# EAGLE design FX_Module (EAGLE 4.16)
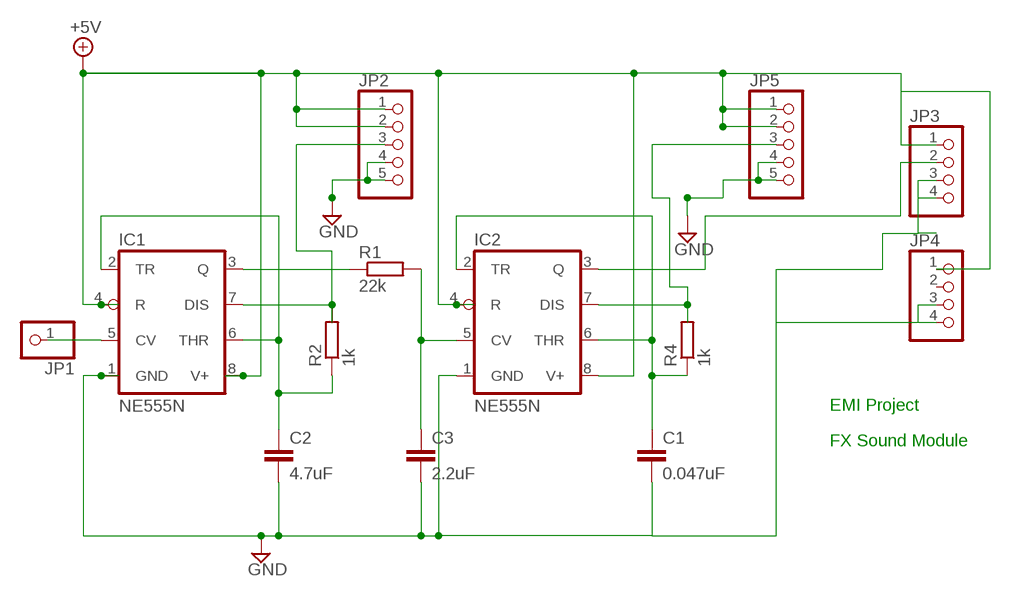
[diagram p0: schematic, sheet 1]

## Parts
C1  0.047uF  C-EU025-024X044  [C025-024X044]
C2  4.7uF  C-EU025-024X044  [C025-024X044]
C3  2.2uF  C-EU025-024X044  [C025-024X044]
IC1  NE555N  [DIL08]
IC2  NE555N  [DIL08]
JP1  PINHD-1X1  [1X01]
JP2  PINHD-1X5  [1X05]
JP3  PINHD-1X4  [1X04]
JP4  PINHD-1X4  [1X04]
JP5  PINHD-1X5  [1X05]
R1  22k  R-EU_0204/7  [0204/7]
R2  1k  R-EU_0204/7  [0204/7]
R4  1k  R-EU_0204/7  [0204/7]

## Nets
+5V: IC1.4(R) IC1.8(V+) IC2.4(R) IC2.8(V+) JP2.1 JP2.2 JP3.1 JP4.1 JP5.1 JP5.2
GND: C1.2 C2.2 C3.2 IC1.1(GND) IC2.1(GND) JP2.4 JP2.5 JP3.3 JP3.4 JP4.3 JP4.4 JP5.4 JP5.5
N$1: C3.1 IC2.5(CV) R1.2
N$2: IC2.7(DIS) JP5.3 R4.2
N$3: IC1.7(DIS) JP2.3 R2.2
N$4: IC2.3(Q) JP3.2
N$6: IC1.5(CV) JP1.1
N$7: C2.1 IC1.2(TR) IC1.6(THR) R2.1
N$8: C1.1 IC2.2(TR) IC2.6(THR) R4.1
N$10: IC1.3(Q) R1.1
Unconnected: JP4.2

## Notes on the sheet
- EMI Project
- FX Sound Module

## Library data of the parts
C1-C3 = rcl:C-EU: CAPACITOR, European symbol
IC1 IC2 = linear:*555: TIMER
JP1 = pinhead:PINHD-1X1: PIN HEADER
JP2 JP5 = pinhead:PINHD-1X5: PIN HEADER
JP3 JP4 = pinhead:PINHD-1X4: PIN HEADER
R1 R2 R4 = rcl:R-EU_: RESISTOR, European symbol

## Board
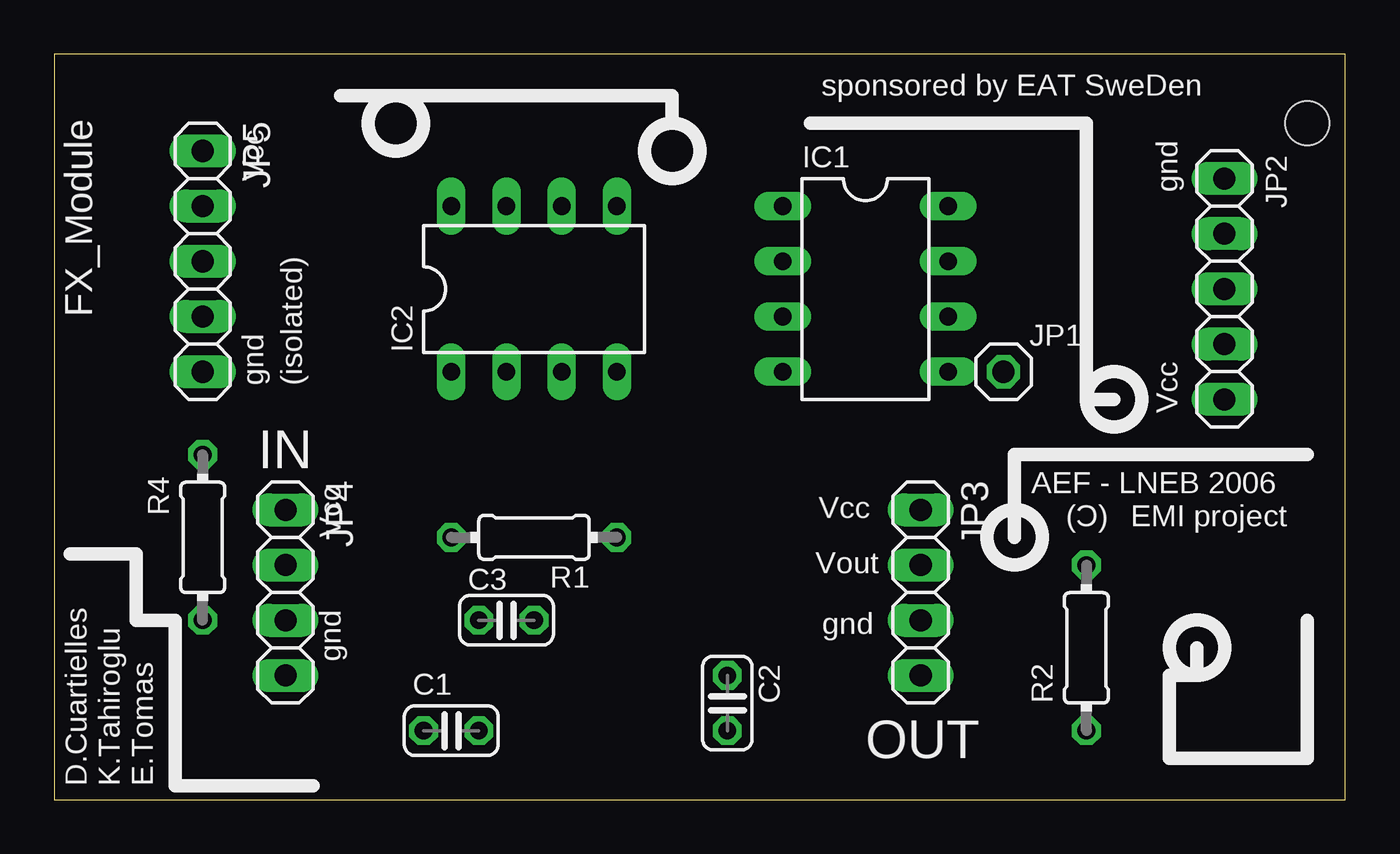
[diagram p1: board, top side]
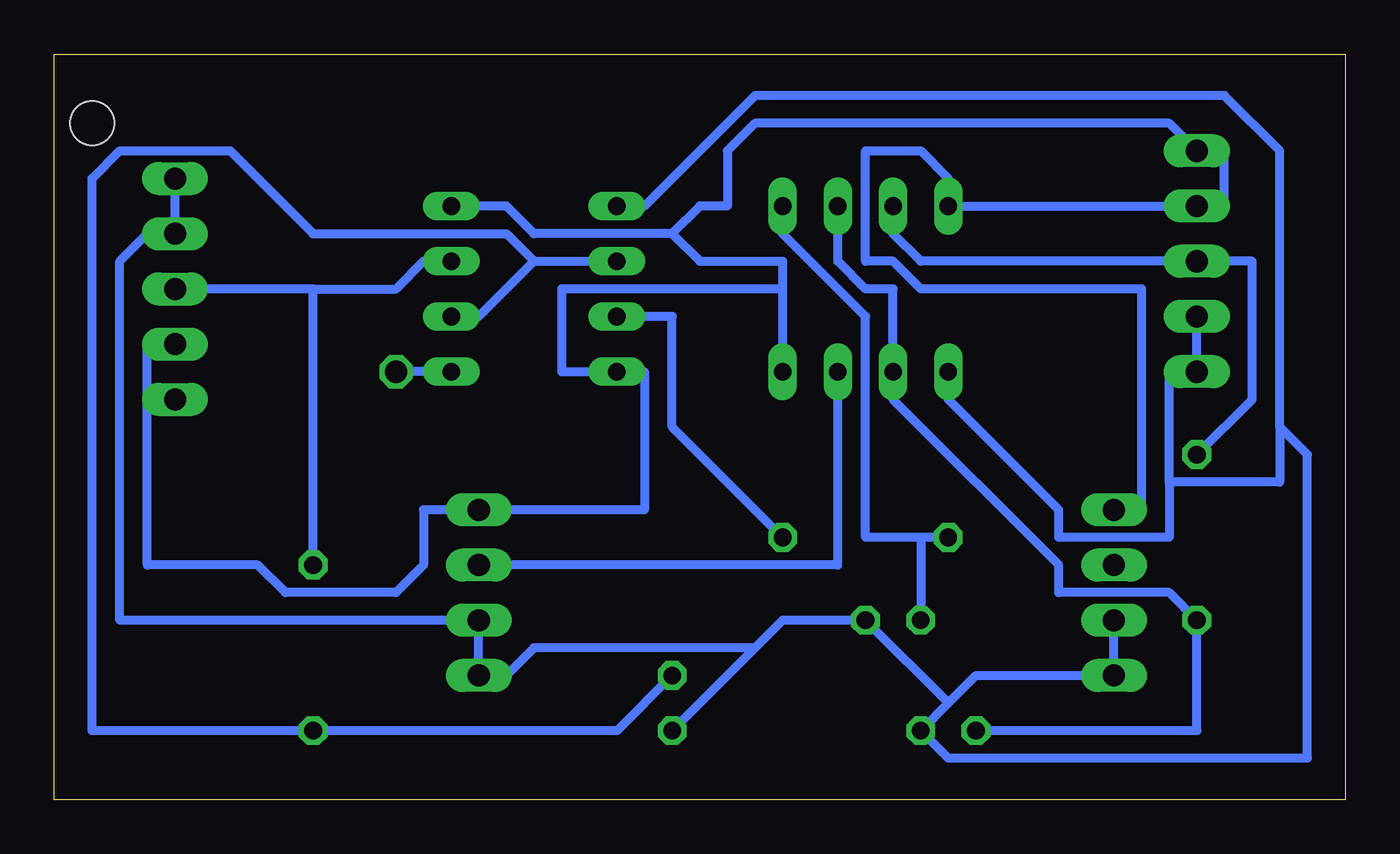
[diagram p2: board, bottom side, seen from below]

Size 59.36 x 34.28 mm. Coordinates in mm from the lower left corner, seen from the top.
Outline: 0,0 59.36,0 59.36,34.28 0,34.28 0,0
Copper layers (1*16): Top 0.035mm / dielectric 1.5mm / Bottom 0.035mm
Design rules "default": minimum track width 10mil, minimum drill 24mil, track to track 8mil, track to pad 8mil, pad to pad 8mil, via to via 8mil, smd to smd 8mil, copper to edge 40mil, drill to drill 8mil, minimum pad ring 10mil, minimum via ring 8mil, stop-mask expansion 4mil, vias tented up to drill 0mil, thermal gap 10mil
Holes 2 mm at 57.62,31.11

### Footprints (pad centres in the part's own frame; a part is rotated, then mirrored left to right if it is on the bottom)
C025-024X044 = drill 0.813 octagon: 1 -1.27,0; 2 1.27,0
DIL08 = drill 0.813 long: 1 -3.81,-3.81; 2 -1.27,-3.81; 3 1.27,-3.81; 4 3.81,-3.81; 5 3.81,3.81; 6 1.27,3.81; 7 -1.27,3.81; 8 -3.81,3.81
1X01 = drill 1.016 octagon: 1 0,0
1X05 = drill 1.016 long: 1 -5.08,0; 2 -2.54,0; 3 0,0; 4 2.54,0; 5 5.08,0
1X04 = drill 1.016 long: 1 -3.81,0; 2 -1.27,0; 3 1.27,0; 4 3.81,0
0204/7 = drill 0.813 octagon: 1 -3.81,0; 2 3.81,0

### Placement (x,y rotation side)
C1  18.25,3.17 0 top
C2  30.95,4.44 270 top
C3  20.79,8.25 0 top
IC1  37.3,23.49 270 top
IC2  22.06,23.49 0 top
JP1  43.65,19.68 0 top
JP2  53.81,23.49 90 top
JP3  39.84,9.52 270 top
JP4  10.63,9.52 270 top
JP5  6.82,24.76 270 top
R1  22.06,12.06 180 top
R2  47.46,6.98 90 top
R4  6.82,12.06 90 top

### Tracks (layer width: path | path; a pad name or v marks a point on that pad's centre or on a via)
+5V
  Bottom 0.406: JP4.1 9.36,13.33 9.36,23.49 19.52,23.49 20.79,24.76 22.06,24.76 22.06,29.84 19.52,29.84 18.25,28.57 IC2.8 JP5.2 5.55,27.3 5.55,29.84 JP5.1 8.09,31.11 27.14,31.11 28.41,29.84 28.41,27.3 29.68,27.3 30.95,26.03 | 25.87,23.49 25.87,24.76 29.68,24.76 30.95,26.03 | 30.95,26.03 37.3,26.03 38.57,27.3 IC1.8 | 25.87,23.49 IC2.4 | 55.08,18.41 55.08,20.95 JP2.2 | 55.08,18.41 55.08,10.79 50,10.79 48.73,9.52 43.65,9.52 42.38,10.79 42.38,13.33 JP3.1 32.22,13.33 32.22,19.68 IC1.4 36.03,19.68 36.03,23.49 25.87,23.49 | 55.08,18.41 JP2.1
GND
  Bottom 0.406: 8.09,14.6 8.09,19.68 JP5.5 JP5.4 | 8.09,14.6 8.09,12.06 13.17,12.06 13.17,13.33 18.25,18.41 IC2.1 | 3.01,17.14 3.01,14.6 8.09,14.6 | 3.01,17.14 3.01,29.84 5.55,32.38 27.14,32.38 32.22,27.3 IC1.1 | JP2.5 JP2.4 55.08,26.03 56.35,24.76 56.35,8.25 JP3.3 JP3.4 38.57,5.71 37.3,6.98 27.14,6.98 | 18.25,4.44 16.98,5.71 JP4.4 JP4.3 | 18.25,4.44 C1.2 18.25,1.9 1.74,1.9 1.74,15.87 3.01,17.14 | 18.25,4.44 C3.2 25.87,8.25 27.14,6.98 | 27.14,6.98 C2.2
N$1
  Bottom 0.406: 19.52,12.06 C3.1 | R1.2 19.52,12.06 | 19.52,12.06 22.06,12.06 22.06,22.22 25.87,26.03 IC2.5
N$2
  Bottom 0.406: R4.2 4.28,18.41 4.28,24.76 JP5.3 19.52,24.76 20.79,26.03 IC2.7
N$3
  Bottom 0.406: R2.2 47.46,23.49 | 47.46,23.49 JP2.3 | 47.46,23.49 43.65,23.49 42.38,24.76 IC1.7
N$4
  Bottom 0.406: IC2.3 23.33,10.79 JP3.2
N$6
  Bottom 0.406: IC1.5 JP1.1
N$7
  Bottom 0.406: 37.3,24.76 39.84,22.22 IC1.6 | 37.3,24.76 IC1.2 | C2.1 33.49,3.17 R2.1 57.62,3.17 57.62,28.57 56.35,29.84 51.27,29.84 47.46,26.03 38.57,26.03 37.3,24.76
N$8
  Bottom 0.406: IC2.6 23.33,24.76 22.06,23.49 20.79,23.49 IC2.2 20.79,18.41 13.17,10.79 13.17,9.52 8.09,9.52 R4.1 6.82,3.17 C1.1
N$10
  Bottom 0.406: R1.1 30.95,17.14 30.95,22.22 IC1.3

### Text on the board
tPlace: sponsored by EAT SweDen | Vcc | gnd | FX_Module | gnd | (isolated) | Vcc | IN | AEF - LNEB 2006 | Vcc | (C) | EMI project | Vcc | Vout | gnd | gnd | OUT | D.Cuartielles | K.Tahiroglu | E.Tomas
